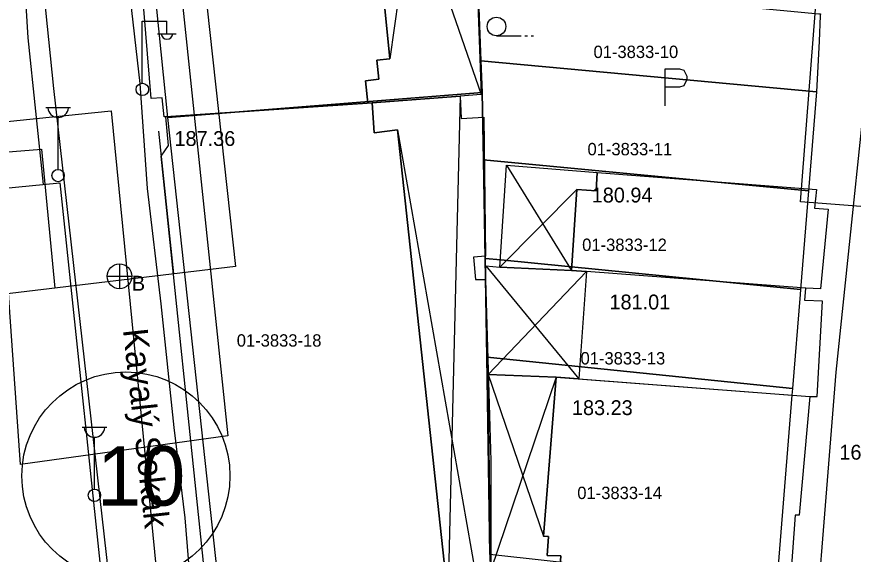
# Model space of a CAD drawing. Extents: x 419101 to 420177, y 4451541 to 4452254.
# Drawn here: x 420036.7 to 420104.2, y 4451666 to 4451709.4 of the extents above; entities that cross this region are included whole.
import ezdxf

# ---------------------------------------------------------------- set-up
doc = ezdxf.new("R2010")
doc.units = 0
for name, color, linetype in [('2_KADASTRO', 7, 'Continuous'), ('3_HALİHAZIR', 7, 'Continuous'), ('Level 10', 7, 'Continuous'), ('Level 27', 7, 'Continuous'), ('Level 58', 7, 'Continuous'), ('Level 9', 7, 'Continuous')]:
    doc.layers.add(name, color=color, linetype=linetype)

# ---------------------------------------------------------------- blocks, each defined once
blk = doc.blocks.new('10')
at = {"layer": 'Level 58'}
blk.add_circle((0, 0), 8.4, dxfattribs=at)
blk.add_text('10', height=4.8, dxfattribs=at).set_placement((-2.342, -2.4))

msp = doc.modelspace()

# ---------------------------------------------------------------- linework, layer by layer
at = {"layer": '2_KADASTRO'}
for points in [[(420045.64, 4451733.16), (420070.72, 4451736.46), (420073.46, 4451735.72), (420073.44, 4451725.17), (420073.89, 4451712.33), (420074.155, 4451705.885), (420074.26, 4451703.34), (420048.87, 4451701.31)], [(420073.89, 4451712.33), (420101.44, 4451709.68), (420101.562, 4451709.668), (420101.555, 4451709.523), (420101.454, 4451707.482), (420101.25, 4451703.376), (420074.155, 4451705.885)], [(420074.155, 4451705.885), (420101.25, 4451703.376), (420100.603, 4451695.39), (420074.351, 4451697.887), (420074.26, 4451703.34)], [(420048.87, 4451701.31), (420074.26, 4451703.34), (420074.351, 4451697.887), (420074.483, 4451689.931), (420074.616, 4451681.959), (420074.881, 4451666.021), (420074.9, 4451664.89), (420074.99, 4451659.67), (420074.994, 4451659.461), (420059.221, 4451663.142), (420059.288, 4451662.044), (420053.18, 4451661.73)], [(420012.108, 4451673.532), (420012.604, 4451698.263), (420012.67, 4451698.576), (420039.285, 4451701.329), (420044.291, 4451701.847), (420058.797, 4451554.171), (420053.84, 4451553.545), (420043.213, 4451552.211), (420027.019, 4451550.161)], [(420074.351, 4451697.887), (420100.603, 4451695.39), (420099.957, 4451687.406), (420075.745, 4451689.806), (420074.483, 4451689.931)], [(420074.483, 4451689.931), (420075.745, 4451689.806), (420099.957, 4451687.406), (420099.926, 4451687.021), (420099.31, 4451679.422), (420074.921, 4451681.928), (420074.616, 4451681.959)], [(420074.616, 4451681.959), (420074.921, 4451681.928), (420099.31, 4451679.422), (420099.265, 4451678.871), (420098.017, 4451663.454), (420074.881, 4451666.021)]]:
    msp.add_lwpolyline(points, close=True, dxfattribs=at)
at = {"layer": '3_HALİHAZIR'}
for p, q in [((420070.982, 4451736.165), (420066.799, 4451706.052)), ((420064.2, 4451732.066), (420074.161, 4451703.153)), ((420046.794, 4451704.101), (420046.794, 4451709.101)), ((420046.794, 4451709.101), (420048.794, 4451709.101)), ((420048.794, 4451708.101), (420048.794, 4451709.101)), ((420048.034, 4451708.061), (420049.534, 4451708.061)), ((420075.404, 4451707.91), (420077.404, 4451707.91)), ((420077.704, 4451707.91), (420077.904, 4451707.91)), ((420078.204, 4451707.91), (420078.404, 4451707.91)), ((420072.463, 4451703.035), (420071.479, 4451662.647)), ((420038.997, 4451702.116), (420040.997, 4451702.116)), ((420039.997, 4451697.116), (420039.997, 4451701.309)), ((420067.408, 4451700.3), (420074.959, 4451657.313)), ((420076.22, 4451697.465), (420081.464, 4451688.955)), ((420075.677, 4451689.223), (420081.909, 4451695.489)), ((420044.958, 4451689.481), (420044.958, 4451687.481)), ((420074.54, 4451689.322), (420082.058, 4451680.192)), ((420082.673, 4451688.865), (420074.745, 4451680.542)), ((420043.958, 4451688.481), (420045.958, 4451688.481)), ((420074.745, 4451680.542), (420079.199, 4451667.501)), ((420080.239, 4451680.332), (420074.958, 4451664.734)), ((420041.935, 4451676.288), (420043.936, 4451676.288)), ((420042.936, 4451671.288), (420042.936, 4451675.481))]:
    msp.add_line(p, q, dxfattribs=at)
for points in [[(420032.741, 4451774.097), (420032.594, 4451772.533), (420032.559, 4451771.606), (420032.613, 4451770.994), (420032.817, 4451770.282), (420033.126, 4451769.528), (420033.513, 4451768.714), (420037.991, 4451759.723), (420039.678, 4451755.552), (420041.085, 4451751.772), (420041.787, 4451749.543), (420042.121, 4451748.487), (420043.084, 4451740.546), (420044.105, 4451727.805), (420044.929, 4451718.693), (420046.605, 4451704.062), (420047.188, 4451695.57), (420048.304, 4451686.266), (420049.353, 4451676.267), (420050.226, 4451668.958), (420051.035, 4451659.044), (420051.758, 4451651.3)], [(420100.444, 4451650.786), (420102.842, 4451680.747), (420106.087, 4451711.948), (420107.283, 4451736.689), (420107.664, 4451738.848), (420108.535, 4451742.808), (420109.332, 4451745.581)], [(420012.142, 4451732.282), (420013.398, 4451734.091), (420015.09, 4451736.017), (420016.544, 4451737.077), (420018.071, 4451737.999), (420019.54, 4451738.563), (420021.218, 4451738.953), (420023.397, 4451739.256), (420025.233, 4451739.406), (420028.151, 4451739.176), (420030.571, 4451738.756), (420031.912, 4451738.384), (420033.346, 4451737.783), (420034.556, 4451737.084), (420035.382, 4451736.369), (420035.97, 4451735.674), (420036.265, 4451735.263), (420036.528, 4451734.835), (420036.541, 4451734.806), (420036.739, 4451734.301), (420036.886, 4451733.897), (420037.806, 4451721.597), (420039.637, 4451703.643), (420044.774, 4451658.155)], [(420037.114, 4451714.823), (420037.553, 4451707.755)], [(420037.553, 4451707.755), (420038.799, 4451695.894)], [(420089.027, 4451705.248), (420090.197, 4451705.248)], [(420089.027, 4451702.248), (420089.027, 4451705.248)], [(420090.197, 4451705.248), (420090.547, 4451705.128), (420090.787, 4451704.638), (420090.787, 4451704.378), (420090.547, 4451703.868), (420090.197, 4451703.768)], [(420090.197, 4451703.768), (420089.027, 4451703.768)], [(420017.101, 4451651.666), (420017.251, 4451654.424), (420017.426, 4451655.72), (420017.425, 4451656.784), (420013.678, 4451693.455), (420040.135, 4451696.024), (420044.104, 4451658.484), (420043.277, 4451658.371), (420043.977, 4451651.382)]]:
    msp.add_lwpolyline(points, dxfattribs=at)
for points in [[(420061.95, 4451735.179), (420070.982, 4451736.165), (420072.989, 4451735.285), (420074.161, 4451703.153), (420072.463, 4451703.035), (420065.361, 4451702.482), (420065.015, 4451702.458), (420064.834, 4451704.265), (420065.916, 4451704.403), (420065.751, 4451705.95), (420066.799, 4451706.052), (420064.2, 4451732.066), (420063.144, 4451731.992), (420063.057, 4451733.841), (420062.055, 4451733.736)], [(420044.539, 4451731.419), (420045.517, 4451731.515), (420045.366, 4451733.26), (420050.814, 4451733.975), (420055.624, 4451734.464), (420061.95, 4451735.179), (420062.055, 4451733.736), (420063.057, 4451733.841), (420063.144, 4451731.992), (420064.2, 4451732.066), (420066.799, 4451706.052), (420065.751, 4451705.95), (420065.916, 4451704.403), (420064.834, 4451704.265), (420065.015, 4451702.458), (420048.693, 4451701.361), (420048.558, 4451701.353), (420048.398, 4451702.904), (420047.504, 4451702.836), (420046.78, 4451711.74), (420046.465, 4451711.722)], [(420065.361, 4451702.482), (420072.463, 4451703.035), (420072.558, 4451701.227), (420074.373, 4451701.34), (420074.527, 4451690.119), (420073.56, 4451690.035), (420073.701, 4451688.212), (420074.512, 4451688.228), (420074.957, 4451673.562), (420074.959, 4451657.313), (420072.731, 4451657.392), (420072.85, 4451660.292), (420069.781, 4451660.984), (420069.593, 4451662.47), (420071.479, 4451662.647), (420067.408, 4451700.3), (420065.53, 4451700.082)], [(420069.781, 4451660.984), (420063.762, 4451662.341), (420063.775, 4451662.539), (420059.206, 4451663.4), (420059.045, 4451662.209), (420052.895, 4451661.844), (420052.859, 4451663.707), (420051.789, 4451664.841), (420048.313, 4451698.192), (420048.921, 4451699.055), (420048.693, 4451701.361), (420065.361, 4451702.482), (420065.53, 4451700.082), (420067.408, 4451700.3), (420071.479, 4451662.647), (420069.593, 4451662.47)], [(420075.677, 4451689.223), (420076.22, 4451697.465), (420083.539, 4451696.852), (420083.445, 4451695.39), (420081.909, 4451695.489), (420081.464, 4451688.955)], [(420082.673, 4451688.865), (420081.464, 4451688.955), (420081.909, 4451695.489), (420083.445, 4451695.39), (420083.539, 4451696.858), (420101.261, 4451695.504), (420101.085, 4451693.979), (420102.197, 4451693.89), (420101.577, 4451687.465), (420100.386, 4451687.53)], [(420074.512, 4451688.228), (420074.54, 4451689.322), (420075.677, 4451689.223), (420081.464, 4451688.955), (420082.673, 4451688.865), (420082.058, 4451680.192), (420080.239, 4451680.332), (420074.745, 4451680.542)], [(420100.717, 4451678.761), (420101.298, 4451678.773), (420101.733, 4451686.466), (420100.311, 4451686.532), (420100.386, 4451687.53), (420082.673, 4451688.865), (420082.058, 4451680.192)], [(420074.745, 4451680.542), (420080.239, 4451680.332), (420079.199, 4451667.501), (420079.594, 4451667.475), (420079.496, 4451665.937), (420080.614, 4451665.894), (420080.498, 4451664.353), (420074.958, 4451664.734)], [(420080.498, 4451664.353), (420080.614, 4451665.894), (420079.496, 4451665.937), (420079.594, 4451667.475), (420079.199, 4451667.501), (420080.239, 4451680.332), (420100.717, 4451678.761), (420099.857, 4451669.195), (420099.525, 4451669.191), (420099.193, 4451664.756), (420098.079, 4451664.796), (420097.925, 4451663.348)]]:
    msp.add_lwpolyline(points, close=True, dxfattribs=at)
for centre, radius in [((420075.404, 4451708.66), 0.75), ((420046.804, 4451703.577), 0.5), ((420039.997, 4451696.616), 0.5), ((420044.958, 4451688.481), 1), ((420042.936, 4451670.788), 0.5)]:
    msp.add_circle(centre, radius, dxfattribs=at)
for centre, radius, start, end in [((420048.794, 4451708.105), 0.474, 184.83843, 355.14641), ((420039.997, 4451702.146), 0.837, 183.298, 356.90719), ((420042.936, 4451676.318), 0.837, 183.298, 356.90719)]:
    msp.add_arc(centre, radius, start, end, dxfattribs=at)
at = {"layer": 'Level 10'}
msp.add_lwpolyline([(420167.291, 4451684.745), (420161.762, 4451695.839), (420120.289, 4451729.36), (420117.438, 4451726.678), (420116.012, 4451693.246), (420099.972, 4451694.498), (420103.715, 4451742.59), (420060.468, 4451778.074), (420043.182, 4451775.929), (420053.716, 4451675.607), (420036.964, 4451673.283), (420035.538, 4451693.664), (420015.222, 4451692.77), (420016.291, 4451685.44), (419931.368, 4451675.776)], dxfattribs=at)
at = {"layer": 'Level 27'}
for points in [[(420049.351, 4451688.678), (420048.128, 4451700.198)], [(420011.13, 4451696.532), (420038.665, 4451698.758)], [(420038.665, 4451698.758), (420039.746, 4451687.528)]]:
    msp.add_lwpolyline(points, dxfattribs=at)
at = {"layer": 'Level 9'}
msp.add_lwpolyline([(420167.24, 4451679.956), (420163.8, 4451678.926), (420159.728, 4451691.971), (420112.119, 4451731.678), (420059.031, 4451774.95), (420044.915, 4451775.227), (420054.335, 4451689.275), (420017.244, 4451684.833), (419969.183, 4451677.077), (419959.772, 4451760.935), (419939.289, 4451759.546), (419944.271, 4451715.674), (419953.405, 4451654.03), (419964.491, 4451545.652), (419986.911, 4451547.873), (419987.366, 4451542.396)], dxfattribs=at)

# ---------------------------------------------------------------- block references
at = {"layer": 'Level 58'}
msp.add_blockref('10', (420045.476, 4451672.356), dxfattribs=at)

# ---------------------------------------------------------------- texts
at = {"layer": '2_KADASTRO'}
for s, p in [('01-3833-10', (420083.243, 4451706.111)), ('01-3833-11', (420082.757, 4451698.253)), ('01-3833-12', (420082.326, 4451690.526)), ('01-3833-18', (420054.43, 4451682.798)), ('01-3833-13', (420082.195, 4451681.358)), ('01-3833-14', (420081.933, 4451670.487))]:
    msp.add_text(s, height=1, dxfattribs=at).set_placement(p)
at = {"layer": '3_HALİHAZIR'}
for s, p in [('187.36 ', (420049.402, 4451699.009)), ('B', (420045.958, 4451687.319))]:
    msp.add_text(s, height=1.2, dxfattribs=at).set_placement(p)
for s, height, rotation, p in [('180.94 ', 1.2, 359.99793, (420083.099, 4451694.443)), ('181.01 ', 1.2, 359.99793, (420084.532, 4451685.804)), ('Kayalý Sokak', 2, 276.26985, (420045.235, 4451684.164)), ('183.23 ', 1.2, 359.99793, (420081.5, 4451677.27)), ('161.29 ', 1.2, 359.99714, (420103.101, 4451673.67))]:
    msp.add_text(s, height=height, rotation=rotation, dxfattribs=at).set_placement(p)

doc.saveas('drawing.dxf')
